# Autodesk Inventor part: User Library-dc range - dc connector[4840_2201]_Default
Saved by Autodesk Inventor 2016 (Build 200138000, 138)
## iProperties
Created: 2012-01
Part Number: User Library-dc range - dc connector[4840_2201]_Default
Document SubType Name: Modeling
Designer: Trevor
Density: 1 g/cm^3
Material: Generic
Appearance: Default
Author: Trevor
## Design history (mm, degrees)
feature "Base1"
feature "Base2"
node "Cut-Extrude2"
node "Dome1"
